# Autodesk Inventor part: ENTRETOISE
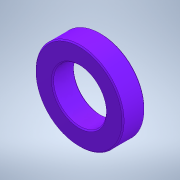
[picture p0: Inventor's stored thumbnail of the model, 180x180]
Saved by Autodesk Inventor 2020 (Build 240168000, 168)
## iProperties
Created: 2003-06
Part Number: ENTRETOISE
Material: Générique
Document SubType Name: Modeling
Designer: Bruno
Density: 1 g/cm^3
Appearance: Par défaut
Author: Bruno
Sending System: SolidWorks 2011
Last Author: Professeur
Last Saved: 2014-11-10
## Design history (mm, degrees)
feature "Chanfrein1"
node "Solide1"
